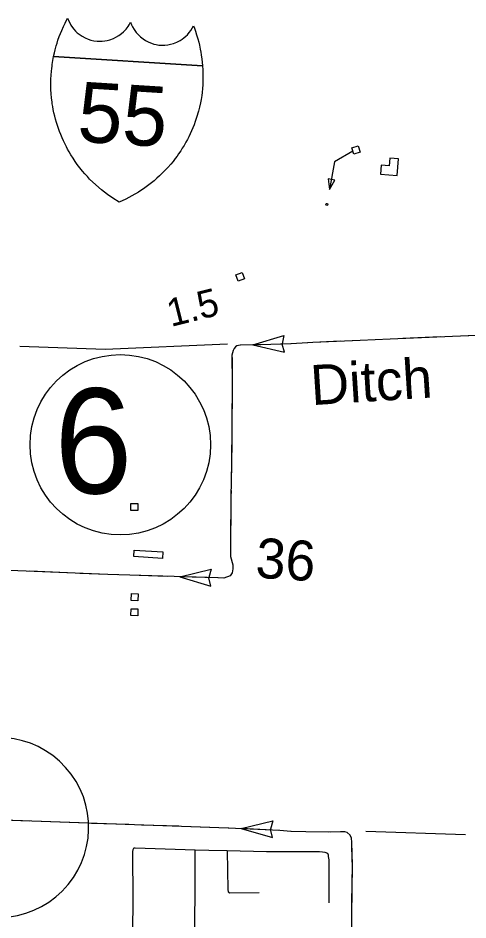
# Model space of a CAD drawing. Extents: x 1366406 to 1373462, y 376856 to 381998.
# Drawn here: x 1369362.7 to 1369439.7, y 380098.9 to 380253.4 of the extents above; entities that cross this region are included whole.
import ezdxf

# ---------------------------------------------------------------- set-up
doc = ezdxf.new("R2010")
doc.units = 0
for name, color, linetype in [('23', 7, 'Continuous'), ('31', 7, 'Continuous'), ('32', 7, 'Continuous'), ('4', 7, 'Continuous'), ('43', 7, 'Continuous'), ('48', 7, 'Continuous'), ('5', 7, 'Continuous'), ('56', 7, 'Continuous'), ('58', 7, 'Continuous'), ('63', 7, 'Continuous'), ('R_Draft', 7, 'Continuous')]:
    doc.layers.add(name, color=color, linetype=linetype)

msp = doc.modelspace()

# ---------------------------------------------------------------- linework, layer by layer
at = {"layer": '23'}
for points in [[(1369368.75, 380246.82), (1369368.89, 380247.42), (1369369.01, 380247.95), (1369369.2, 380248.64), (1369369.33, 380249.09), (1369369.5, 380249.62), (1369369.72, 380250.24), (1369369.92, 380250.75), (1369370.13, 380251.29), (1369370.42, 380251.94), (1369370.71, 380252.55), (1369370.95, 380253.03), (1369371.14, 380253.4), (1369371.31, 380252.97), (1369371.5, 380252.57), (1369371.71, 380252.19), (1369372, 380251.77), (1369372.23, 380251.48), (1369372.51, 380251.17), (1369372.8, 380250.89), (1369373.12, 380250.63), (1369373.63, 380250.28), (1369374.16, 380249.99), (1369374.64, 380249.79), (1369375.11, 380249.63), (1369375.63, 380249.51), (1369376.23, 380249.44), (1369376.63, 380249.42), (1369377.09, 380249.43), (1369377.5, 380249.48), (1369377.94, 380249.56), (1369378.39, 380249.68), (1369379, 380249.9), (1369379.42, 380250.1), (1369379.91, 380250.39), (1369380.39, 380250.75), (1369380.74, 380251.06), (1369381.15, 380251.5), (1369381.49, 380251.94), (1369381.69, 380252.26), (1369381.92, 380252.68)], [(1369381.92, 380252.68), (1369382.09, 380252.23), (1369382.26, 380251.89), (1369382.54, 380251.41), (1369382.89, 380250.93), (1369383.2, 380250.57), (1369383.63, 380250.16), (1369384.08, 380249.81), (1369384.47, 380249.55), (1369385.05, 380249.26), (1369385.48, 380249.09), (1369385.9, 380248.95), (1369386.31, 380248.86), (1369386.76, 380248.78), (1369387.16, 380248.75), (1369387.77, 380248.75), (1369388.29, 380248.81), (1369388.78, 380248.9), (1369389.29, 380249.04), (1369389.84, 380249.26), (1369390.39, 380249.55), (1369390.74, 380249.77), (1369391.06, 380250.01), (1369391.39, 380250.28), (1369391.65, 380250.54), (1369391.98, 380250.92), (1369392.24, 380251.27), (1369392.49, 380251.65), (1369392.7, 380252.05), (1369392.85, 380251.65), (1369393.03, 380251.15), (1369393.24, 380250.51), (1369393.44, 380249.83), (1369393.59, 380249.27), (1369393.72, 380248.73), (1369393.85, 380248.09), (1369393.96, 380247.54), (1369394.03, 380247.08), (1369394.13, 380246.38), (1369394.2, 380245.83), (1369394.25, 380245.22)], [(1369379.99, 380221.87), (1369378.91, 380222.53), (1369377.96, 380223.19), (1369376.93, 380223.98), (1369375.97, 380224.81), (1369374.92, 380225.82), (1369374.53, 380226.23), (1369374.09, 380226.72), (1369373.69, 380227.19), (1369373.25, 380227.74), (1369372.81, 380228.31), (1369372.45, 380228.82), (1369372.07, 380229.39), (1369371.72, 380229.95), (1369371.42, 380230.46), (1369371.15, 380230.93), (1369370.94, 380231.33), (1369370.65, 380231.89), (1369370.43, 380232.36), (1369370.19, 380232.89), (1369369.96, 380233.45), (1369369.76, 380233.96), (1369369.58, 380234.46), (1369369.39, 380235.01), (1369369.23, 380235.52), (1369369.08, 380236.06), (1369368.94, 380236.61), (1369368.81, 380237.18), (1369368.69, 380237.73), (1369368.6, 380238.24), (1369368.52, 380238.7), (1369368.48, 380239.04), (1369368.39, 380239.69), (1369368.32, 380240.45), (1369368.28, 380241.08), (1369368.27, 380241.74), (1369368.27, 380242.28), (1369368.29, 380242.95), (1369368.32, 380243.59), (1369368.37, 380244.29), (1369368.42, 380244.75), (1369368.48, 380245.17), (1369368.51, 380245.43), (1369368.62, 380246.12), (1369368.75, 380246.82)], [(1369394.25, 380245.22), (1369368.75, 380246.82)], [(1369368.75, 380246.82), (1369394.25, 380245.22)], [(1369394.25, 380245.22), (1369394.3, 380244.51), (1369394.32, 380243.82), (1369394.32, 380243.55), (1369394.32, 380243.12), (1369394.31, 380242.66), (1369394.28, 380241.96), (1369394.23, 380241.33), (1369394.17, 380240.65), (1369394.1, 380240.12), (1369394, 380239.47), (1369393.88, 380238.85), (1369393.72, 380238.11), (1369393.56, 380237.47), (1369393.46, 380237.13), (1369393.33, 380236.69), (1369393.18, 380236.19), (1369393, 380235.67), (1369392.79, 380235.12), (1369392.58, 380234.58), (1369392.36, 380234.07), (1369392.14, 380233.58), (1369391.89, 380233.06), (1369391.65, 380232.59), (1369391.39, 380232.11), (1369391.09, 380231.58), (1369390.78, 380231.08), (1369390.51, 380230.65), (1369390.15, 380230.13), (1369389.89, 380229.75), (1369389.57, 380229.32), (1369389.2, 380228.85), (1369388.79, 380228.35), (1369388.33, 380227.82), (1369387.91, 380227.37), (1369387.41, 380226.86), (1369386.9, 380226.36), (1369386.44, 380225.94), (1369385.95, 380225.51), (1369385.51, 380225.16), (1369384.35, 380224.29), (1369383.29, 380223.58), (1369382.16, 380222.92), (1369381.14, 380222.39), (1369379.99, 380221.87)]]:
    msp.add_lwpolyline(points, dxfattribs=at)
at = {"layer": '31'}
for points in [[(1369392.89, 380073.07), (1369392.92, 380091.59), (1369392.98, 380110.85), (1369382.74, 380111.2), (1369382.51, 380111.16), (1369382.43, 380111.11), (1369382.35, 380111.02), (1369382.3, 380110.88), (1369382.28, 380110.58), (1369382.29, 380102.21), (1369382.18, 380091.87), (1369382.12, 380073.46)], [(1369415.9, 380101.83), (1369415.91, 380103.7), (1369415.9, 380109.2), (1369415.83, 380109.77), (1369415.83, 380109.99), (1369415.7, 380110.28), (1369415.24, 380110.45), (1369414.76, 380110.52), (1369414.26, 380110.54), (1369405.17, 380110.55), (1369398.49, 380110.72), (1369395.32, 380110.76), (1369392.98, 380110.85)]]:
    msp.add_lwpolyline(points, dxfattribs=at)
at = {"layer": '32'}
msp.add_lwpolyline([(1369398.49, 380110.72), (1369398.59, 380104.1), (1369398.63, 380103.67), (1369398.92, 380103.5), (1369403.97, 380103.58)], dxfattribs=at)
at = {"layer": '4'}
msp.add_lwpolyline([(1369439.29, 380113.46), (1369422.23, 380114.02)], dxfattribs=at)
at = {"layer": '43'}
for p, q in [((1369402.87, 380197.4), (1369408.19, 380199.01)), ((1369408.19, 380199.01), (1369407.86, 380197.57)), ((1369402.87, 380197.4), (1369408.29, 380196.14)), ((1369408.29, 380196.14), (1369407.86, 380197.55)), ((1369390.34, 380157.68), (1369395.75, 380158.95)), ((1369395.75, 380158.95), (1369395.33, 380157.53)), ((1369390.34, 380157.68), (1369395.66, 380156.07)), ((1369395.66, 380156.07), (1369395.33, 380157.51)), ((1369400.88, 380114.52), (1369406.27, 380115.86)), ((1369406.27, 380115.86), (1369405.86, 380114.44)), ((1369400.88, 380114.52), (1369406.22, 380112.99)), ((1369406.22, 380112.99), (1369405.86, 380114.42))]:
    msp.add_line(p, q, dxfattribs=at)
for points in [[(1369442.42, 380199.08), (1369426.35, 380198.41), (1369421.24, 380198.18), (1369413.12, 380197.81), (1369409.43, 380197.61), (1369404.25, 380197.44), (1369400.67, 380197.37), (1369400.11, 380197.23), (1369399.91, 380197.09), (1369399.64, 380196.79), (1369399.47, 380196.45), (1369399.29, 380195.64), (1369399.32, 380190.94), (1369399.21, 380176.81), (1369399.11, 380171.35), (1369399.07, 380169.04), (1369399.01, 380163.77), (1369399.04, 380161.16), (1369399.41, 380159.73), (1369399.46, 380159.06), (1369399.34, 380158.34), (1369398.99, 380157.84), (1369397.92, 380157.46), (1369396.9, 380157.48), (1369378.01, 380158.05), (1369354.16, 380159.05)], [(1369426.37, 380198.41), (1369426.35, 380198.41), (1369421.24, 380198.18), (1369419.96, 380198.12)], [(1369434.92, 380198.76), (1369428.51, 380198.5)], [(1369441.2, 380199.03), (1369437.05, 380198.85)], [(1369400.73, 380197.37), (1369400.67, 380197.37), (1369400.11, 380197.23), (1369399.91, 380197.09), (1369399.64, 380196.79), (1369399.47, 380196.45), (1369399.29, 380195.64), (1369399.3, 380194.93)], [(1369409.28, 380197.61), (1369404.25, 380197.44), (1369402.87, 380197.41)], [(1369417.83, 380198.02), (1369413.12, 380197.81), (1369411.42, 380197.72)], [(1369399.3, 380194.93), (1369399.32, 380191.72)], [(1369399.31, 380189.58), (1369399.26, 380183.17)], [(1369399.24, 380181.03), (1369399.21, 380176.81), (1369399.17, 380174.62)], [(1369399.13, 380172.48), (1369399.11, 380171.35), (1369399.07, 380169.04), (1369399.03, 380166.06)], [(1369399.01, 380163.93), (1369399.01, 380163.77), (1369399.04, 380161.16), (1369399.41, 380159.73), (1369399.46, 380159.06), (1369399.34, 380158.34), (1369398.99, 380157.84), (1369398.83, 380157.79)], [(1369371.11, 380158.34), (1369364.7, 380158.61)], [(1369379.65, 380158), (1369378.01, 380158.05), (1369373.24, 380158.25)], [(1369385, 380157.84), (1369381.79, 380157.94)], [(1369388.2, 380157.74), (1369385, 380157.84)], [(1369396.75, 380157.48), (1369390.34, 380157.68)], [(1369419.67, 380091.07), (1369419.91, 380108.25), (1369419.79, 380112.23), (1369419.77, 380112.92), (1369419.5, 380113.43), (1369419.01, 380113.84), (1369418.59, 380113.98), (1369417.89, 380113.99), (1369416.12, 380113.91), (1369411.92, 380113.99), (1369409.37, 380114.02), (1369407.47, 380114.22), (1369398.64, 380114.63), (1369350.53, 380116.29)], [(1369364.55, 380115.8), (1369361.67, 380115.9)], [(1369373.1, 380115.51), (1369366.68, 380115.73)], [(1369381.64, 380115.21), (1369375.23, 380115.43)], [(1369390.19, 380114.92), (1369383.78, 380115.14)], [(1369398.74, 380114.62), (1369398.64, 380114.63), (1369392.33, 380114.84)], [(1369404.08, 380114.38), (1369400.88, 380114.52)], [(1369407.29, 380114.23), (1369404.08, 380114.38)], [(1369415.83, 380113.91), (1369411.92, 380113.99), (1369409.41, 380114.02)], [(1369419.89, 380108.79), (1369419.79, 380112.23), (1369419.77, 380112.92), (1369419.5, 380113.43), (1369419.01, 380113.84), (1369418.59, 380113.98), (1369417.96, 380113.99)], [(1369419.8, 380100.24), (1369419.89, 380106.65)]]:
    msp.add_lwpolyline(points, dxfattribs=at)
at = {"layer": '5'}
msp.add_lwpolyline([(1369398.54, 380197.53), (1369377.58, 380196.61), (1369362.97, 380197.14)], dxfattribs=at)
at = {"layer": '56'}
msp.add_lwpolyline([(1369419.96, 380230.61), (1369416.84, 380228.76), (1369416.01, 380224.03)], dxfattribs=at)
for points in [[(1369420.14, 380230.05), (1369419.78, 380231.16), (1369420.9, 380231.52), (1369421.26, 380230.41)], [(1369416.87, 380225.63), (1369415.74, 380225.83), (1369416.01, 380224.03)], [(1369400.36, 380208.3), (1369399.92, 380209.38), (1369401.01, 380209.82), (1369401.45, 380208.74)], [(1369381.98, 380169.03), (1369381.98, 380170.2), (1369383.15, 380170.2), (1369383.15, 380169.03)], [(1369382.49, 380161.12), (1369382.56, 380162.24), (1369387.47, 380161.94), (1369387.4, 380160.81)], [(1369382.02, 380153.63), (1369382.07, 380154.8), (1369383.24, 380154.74), (1369383.19, 380153.57)], [(1369381.97, 380151.03), (1369382.02, 380152.2), (1369383.19, 380152.16), (1369383.15, 380150.99)]]:
    msp.add_lwpolyline(points, close=True, dxfattribs=at)
msp.add_circle((1369415.53, 380221.48), 0.169, dxfattribs=at)
at = {"layer": '58'}
msp.add_lwpolyline([(1369427.58, 380226.44), (1369427.81, 380229.29), (1369426.3, 380229.41), (1369426.2, 380228.06), (1369424.85, 380228.17), (1369424.73, 380226.67)], close=True, dxfattribs=at)
at = {"layer": '63'}
msp.add_arc((1369359.34, 380114.73), 15.41, 228.0896, 128.8034, dxfattribs=at)
at = {"layer": 'R_Draft'}
msp.add_circle((1369380.16, 380180.3), 15.45, dxfattribs=at)

# ---------------------------------------------------------------- texts
at = {"layer": '23'}
msp.add_text('55', height=10.29, rotation=356.4139, dxfattribs=at).set_placement((1369372.65, 380232.26))
at = {"layer": '43'}
msp.add_text('Ditch', height=6.843, rotation=3.6554, dxfattribs=at).set_placement((1369412.95, 380187.07))
at = {"layer": '48'}
msp.add_text('1.5', height=4.752, rotation=14.0746, dxfattribs=at).set_placement((1369388.84, 380200.46))
at = {"layer": '5'}
msp.add_text('36', height=6.843, rotation=356.4139, dxfattribs=at).set_placement((1369403.2, 380157.53))
at = {"layer": 'R_Draft'}
msp.add_text('6', height=18, dxfattribs=at).set_placement((1369368.86, 380171.95))

doc.saveas('drawing.dxf')
